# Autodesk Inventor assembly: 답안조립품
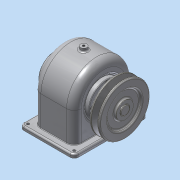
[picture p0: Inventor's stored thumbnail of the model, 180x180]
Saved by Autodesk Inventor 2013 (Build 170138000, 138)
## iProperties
Created: 2016-01
Part Number: 답안조립품
Document SubType Name: Assembly
Designer: Administrator
Author: Administrator
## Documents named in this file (16)
- C:\Users\Administrator\Desktop\460106V1011\답안조립품.iam
- C:\Users\Administrator\Desktop\460106V1011\본체.ipt
- C:\Users\Administrator\Desktop\460106V1011\앞커버.ipt
- C:\Users\Administrator\Desktop\460106V1011\뒤커버.ipt
- C:\Users\Administrator\Desktop\460106V1011\베어링 6203.ipt
- C:\Users\Administrator\Desktop\460106V1011\부시1.ipt
- C:\Users\Administrator\Desktop\460106V1011\부시2.ipt
- C:\Users\Administrator\Desktop\460106V1011\볼트 M3 x 8.ipt
- C:\Users\Administrator\Desktop\460106V1011\볼트 M3 x 10.ipt
- C:\Users\Administrator\Desktop\460106V1011\축.ipt
- C:\Users\Administrator\Desktop\460106V1011\V-벨트풀리.ipt
- C:\Users\Administrator\Desktop\460106V1011\스퍼기어.ipt
- C:\Users\Administrator\Desktop\460106V1011\오일씰 28 40 8.ipt
- C:\Users\Administrator\Desktop\460106V1011\키 - 6 x 6 x 22.ipt
- C:\Users\Administrator\Desktop\460106V1011\키 - 5 x 5 x 18.ipt
- C:\Users\Administrator\Desktop\460106V1011\멈춤나사 - M4x10.ipt
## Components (9 placed, 3 different names)
1. V-벨트풀리:1
2. ISO 4762 M3 x 8:1
3. ISO 4762 M3 x 8:2
4. ISO 4762 M3 x 8:3
5. ISO 4762 M3 x 8:4
6. ISO 4762 M3 x 10:1
7. ISO 4762 M3 x 10:2
8. ISO 4762 M3 x 10:3
9. ISO 4762 M3 x 10:4
